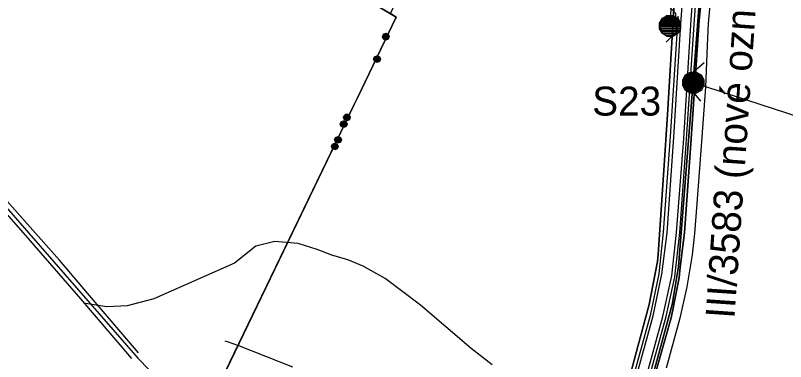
# Model space of a CAD drawing. Extents: x -645676 to -642474, y -1077513 to -1072613.
# Drawn here: x -644954.9 to -644556.1, y -1075498.4 to -1075319 of the extents above; entities that cross this region are included whole.
import ezdxf

# ---------------------------------------------------------------- set-up
doc = ezdxf.new("R2010")
doc.units = 0
for name, color, linetype in [('_cesty_Kunci', 7, 'Continuous'), ('Kanalizace', 7, 'Continuous'), ('KULTURY_STAV', 7, 'Continuous'), ('OBVOD_PU', 7, 'Continuous'), ('P__kop___st_vaj_c_', 7, 'Continuous'), ('PC_MIMO_OBV', 7, 'Continuous'), ('PC_NAVRH', 7, 'Continuous'), ('PC_OBJ_POPIS_NAVRH', 7, 'Continuous'), ('PC_OBJEKTY_NAVRH', 7, 'Continuous'), ('PC_STAN_NAVRH', 7, 'Continuous'), ('Popis_silnice_II__a_III__t__dy', 7, 'Continuous'), ('SDELOVACI', 7, 'Continuous'), ('Silnice_II__t__dy_a_III__t__dy', 7, 'Continuous'), ('SPRAV_HR_STAV', 7, 'Continuous'), ('VODOVOD', 7, 'Continuous'), ('VRSTEVNICE', 7, 'Continuous')]:
    doc.layers.add(name, color=color, linetype=linetype)

# ---------------------------------------------------------------- blocks, each defined once
blk = doc.blocks.new('$406')
blk.add_lwpolyline([(-0.19, 0.72), (0.2, 0.72), (0.54, 0.53), (0.73, 0.19), (0.73, -0.2), (0.54, -0.54), (0.2, -0.73), (-0.19, -0.73), (-0.53, -0.54), (-0.72, -0.2), (-0.72, 0.19), (-0.53, 0.53), (-0.2, 0.72), (-0.28, 0.64), (0.28, 0.64), (0.44, 0.56), (-0.44, 0.56), (-0.52, 0.48), (0.52, 0.48), (0.56, 0.4), (-0.55, 0.4), (-0.6, 0.32), (0.6, 0.32), (0.68, 0.24), (-0.59, 0.24), (-0.65, 0.24), (-0.68, 0.16), (0.59, 0.16), (0.68, 0.16), (0.68, 0.08), (-0.59, 0.08), (-0.68, 0.08), (-0.68, 0), (0.59, 0), (0.68, 0), (0.68, -0.08), (-0.59, -0.08), (-0.68, -0.08), (-0.68, -0.16), (0.59, -0.16), (0.68, -0.16), (0.65, -0.24), (-0.62, -0.24), (-0.65, -0.24), (-0.6, -0.32), (0.6, -0.32), (0.56, -0.4), (-0.55, -0.4), (-0.52, -0.48), (0.52, -0.48), (0.44, -0.56), (-0.44, -0.56), (-0.28, -0.64), (0.28, -0.64), (-0.02, -0.69)])
blk = doc.blocks.new('$935')
blk.add_lwpolyline([(-2, -1), (-1, 0), (1, 0), (2, -1)])
blk = doc.blocks.new('2$0620')
for points in [[(-1.07, 0.32), (-0.88, 0.13), (-0.88, -0.14), (-1.07, -0.33), (-1.34, -0.33), (-1.53, -0.14), (-1.53, 0.13), (-1.34, 0.32), (-1.07, 0.32), (-1.08, 0.28), (-1.32, 0.28), (-1.4, 0.2), (-1, 0.2), (-0.92, 0.12), (-1.48, 0.12), (-1.48, 0.04), (-0.92, 0.04), (-0.92, -0.04), (-1.48, -0.04), (-1.48, -0.12), (-0.92, -0.12), (-1, -0.2), (-1.4, -0.2), (-1.32, -0.28), (-1.08, -0.28)], [(1.43, 0.32), (1.62, 0.13), (1.62, -0.14), (1.43, -0.33), (1.16, -0.33), (0.97, -0.14), (0.97, 0.13), (1.16, 0.32), (1.43, 0.32), (1.4, 0.28), (1.16, 0.28), (1.08, 0.2), (1.48, 0.2), (1.56, 0.12), (1, 0.12), (1, 0.04), (1.56, 0.04), (1.56, -0.04), (1, -0.04), (1, -0.12), (1.56, -0.12), (1.48, -0.2), (1.08, -0.2), (1.16, -0.28), (1.4, -0.28)]]:
    blk.add_lwpolyline(points)

msp = doc.modelspace()

# ---------------------------------------------------------------- linework, layer by layer
at = {"layer": '_cesty_Kunci'}
for points in [[(-644891.19, -1075493.8), (-644917.56, -1075462.89), (-644932.09, -1075445.84), (-644947.3, -1075428.72), (-644979.37, -1075392.6), (-645001.52, -1075368.67), (-645051.49, -1075312.64), (-645077.68, -1075284.72), (-645088.58, -1075274.1), (-645102.77, -1075260.47)], [(-644894.59, -1075496.75), (-644920.98, -1075465.81), (-644950.66, -1075431.71), (-644982.71, -1075395.62), (-645004.85, -1075371.7), (-645054.81, -1075315.68), (-645080.9, -1075287.87), (-645091.72, -1075277.32), (-645105.75, -1075264.09)]]:
    msp.add_lwpolyline(points, dxfattribs=at)
at = {"layer": 'Kanalizace'}
for p, q in [((-644846.48, -1075487.59), (-644845.19, -1075488.05)), ((-644845.19, -1075488.05), (-644839.37, -1075490.12))]:
    msp.add_line(p, q, dxfattribs=at)
at = {"layer": 'KULTURY_STAV'}
for points in [[(-644641.24, -1075565.84), (-644614.92, -1075468.8), (-644611.62, -1075449.05), (-644602.57, -1075335.69), (-644598.94, -1075287.94), (-644594.67, -1075231.99), (-644593.88, -1075221.64), (-644593.31, -1075217.27), (-644591.32, -1075202.08), (-644570.53, -1075092.51), (-644563.77, -1075059.63)], [(-644563.77, -1075059.63), (-644570.53, -1075092.51), (-644591.32, -1075202.08), (-644593.31, -1075217.27), (-644593.88, -1075221.64), (-644594.67, -1075231.99), (-644598.94, -1075287.94), (-644602.57, -1075335.69), (-644611.62, -1075449.05), (-644614.92, -1075468.8), (-644641.24, -1075565.84)], [(-644851.08, -1075513.74), (-644779.52, -1075365.17), (-644777.84, -1075361.69), (-644757.68, -1075319.84), (-644760.71, -1075318.03), (-644746.53, -1075289.08), (-644737.59, -1075267.05), (-644736.8, -1075264.15), (-644692.33, -1075274.04), (-644655.11, -1075281.83), (-644643, -1075284.37), (-644621.33, -1075289.98), (-644615.66, -1075293.05), (-644612.56, -1075292.62), (-644616.89, -1075364.66), (-644616.92, -1075365.04), (-644618.52, -1075388.88), (-644622.17, -1075442.97), (-644622.41, -1075446.47), (-644626.67, -1075468.75), (-644631.36, -1075486.14), (-644660.63, -1075594.71)], [(-644660.63, -1075594.71), (-644631.36, -1075486.14), (-644626.67, -1075468.75), (-644622.41, -1075446.47), (-644622.17, -1075442.97), (-644618.52, -1075388.88), (-644616.92, -1075365.04), (-644616.89, -1075364.66), (-644612.56, -1075292.62)], [(-644599.35, -1075305.97), (-644600.88, -1075321.39), (-644605.07, -1075382.91), (-644608.52, -1075431.72), (-644610.65, -1075449.53), (-644611.3, -1075455.01), (-644614.01, -1075468.82), (-644614.04, -1075468.97), (-644615.38, -1075475.8), (-644632.93, -1075537.98)], [(-644632.93, -1075537.98), (-644615.38, -1075475.8), (-644614.04, -1075468.97), (-644614.01, -1075468.82), (-644611.3, -1075455.01), (-644610.65, -1075449.53), (-644608.52, -1075431.72), (-644605.07, -1075382.91), (-644600.88, -1075321.39), (-644599.35, -1075305.97)]]:
    msp.add_lwpolyline(points, dxfattribs=at)
at = {"layer": 'OBVOD_PU'}
msp.add_lwpolyline([(-644851.08, -1075513.74), (-644779.52, -1075365.17), (-644777.84, -1075361.69), (-644757.68, -1075319.84), (-644795.04, -1075297.48), (-644820.35, -1075282.33), (-644850.33, -1075263.32), (-644852.84, -1075262.37), (-644862.38, -1075258.74), (-644863.9, -1075253.24), (-644872.26, -1075252.25), (-644876.28, -1075250.21), (-644887.03, -1075244.75), (-644897.16, -1075239.61), (-644908.34, -1075233.93), (-644928.8, -1075223.41), (-644931.18, -1075222.19), (-644945.57, -1075214.79), (-644951.22, -1075211.54), (-644979.55, -1075195.21)], dxfattribs=at)
at = {"layer": 'P__kop___st_vaj_c_'}
for points in [[(-644655.14, -1075609.48), (-644653.46, -1075602.68), (-644648.86, -1075585.89), (-644635.16, -1075537.38), (-644617.89, -1075475.06), (-644613.54, -1075454.44), (-644610.92, -1075431.54), (-644607.37, -1075383.08), (-644603.3, -1075321.13), (-644601.93, -1075302.47), (-644601.06, -1075291.71), (-644597.72, -1075247.83), (-644595.19, -1075217.3), (-644590.26, -1075186), (-644583.34, -1075151.35), (-644580.44, -1075136.31), (-644575.79, -1075111.27), (-644571.92, -1075092.46)], [(-644611.93, -1075319.33), (-644612.35, -1075328.45), (-644615.83, -1075381.83), (-644619.58, -1075431.28), (-644621.78, -1075452.89), (-644626.25, -1075474.56), (-644642.84, -1075534.64), (-644656.72, -1075584.46), (-644659.11, -1075593.34), (-644661.97, -1075602.58)]]:
    msp.add_lwpolyline(points, dxfattribs=at)
at = {"layer": 'PC_MIMO_OBV'}
for points in [[(-645105.18, -1075262.04), (-645061.38, -1075305.82), (-644985.84, -1075388.74), (-644891.59, -1075496.61)], [(-644891.59, -1075496.61), (-644874.04, -1075514.58), (-644860.84, -1075525.2), (-644849.97, -1075529.08), (-644838.34, -1075530.9)]]:
    msp.add_lwpolyline(points, dxfattribs=at)
at = {"layer": 'PC_NAVRH'}
for points in [[(-644615.94, -1075324.38), (-644614.35, -1075298.06), (-644618.37, -1075293.21), (-644622.69, -1075291.24), (-644738.79, -1075265.15), (-644794.9, -1075254.19), (-644881.17, -1075235.85), (-644890.64, -1075231.29), (-644935.93, -1075197.93), (-645029.58, -1075127.01), (-645122.98, -1075056.71), (-645236.69, -1074970.28), (-645321.72, -1074906.75)], [(-644603.95, -1075353.79), (-644272.56, -1075461.49), (-643996.74, -1075550.91)]]:
    msp.add_lwpolyline(points, dxfattribs=at)
at = {"layer": 'SDELOVACI'}
msp.add_lwpolyline([(-644560.38, -1075075.22), (-644564.89, -1075096.59), (-644567.03, -1075108.6), (-644571.32, -1075129.12), (-644575.46, -1075151.85), (-644577.56, -1075163.27), (-644585.27, -1075204.39), (-644588.56, -1075234.74), (-644591.74, -1075269.83), (-644593.41, -1075290.49), (-644593.66, -1075294.47), (-644596.25, -1075323.14), (-644596.67, -1075334.53), (-644597.63, -1075356.25), (-644600.03, -1075389.03), (-644602.22, -1075418.8), (-644603.31, -1075432), (-644604.47, -1075443.16), (-644607.26, -1075459.62), (-644610.89, -1075475.88), (-644617.87, -1075501.8)], dxfattribs=at)
at = {"layer": 'Silnice_II__t__dy_a_III__t__dy'}
for p, q in [((-644610.11, -1075320.89), (-644608.84, -1075302.23)), ((-644605.01, -1075321.1), (-644603.5, -1075302.41)), ((-644610.45, -1075326), (-644610.11, -1075320.89)), ((-644608.82, -1075382.75), (-644605.01, -1075321.1)), ((-644613.99, -1075382.07), (-644610.45, -1075326)), ((-644617.5, -1075431.67), (-644613.99, -1075382.07)), ((-644612.53, -1075431.45), (-644608.82, -1075382.75)), ((-644620.14, -1075453.12), (-644617.5, -1075431.67)), ((-644615.08, -1075454.01), (-644612.53, -1075431.45)), ((-644624.75, -1075474.74), (-644620.14, -1075453.12)), ((-644619.69, -1075475.08), (-644615.08, -1075454.01)), ((-644641.27, -1075535.22), (-644624.75, -1075474.74)), ((-644636.65, -1075536.99), (-644619.69, -1075475.08))]:
    msp.add_line(p, q, dxfattribs=at)
at = {"layer": 'SPRAV_HR_STAV'}
for p, q in [((-644795.04, -1075297.48), (-644757.68, -1075319.84)), ((-644757.68, -1075319.84), (-644777.84, -1075361.69)), ((-644779.52, -1075365.17), (-644851.08, -1075513.74)), ((-644777.84, -1075361.69), (-644779.52, -1075365.17))]:
    msp.add_line(p, q, dxfattribs=at)
at = {"layer": 'VODOVOD'}
msp.add_line((-644839.37, -1075490.12), (-644811.45, -1075501.1), dxfattribs=at)
at = {"layer": 'VRSTEVNICE'}
msp.add_lwpolyline([(-644708.13, -1075500.09), (-644719, -1075491.6), (-644745.22, -1075469.15), (-644763.46, -1075455.39), (-644774.9, -1075448.87), (-644782.85, -1075445.63), (-644791.12, -1075443.23), (-644798.7, -1075440.29), (-644808.57, -1075437.23), (-644820.51, -1075436.21), (-644830.39, -1075438.66), (-644841.52, -1075447.43), (-644883.23, -1075465.96), (-644897.13, -1075469.58), (-644907.56, -1075470.02), (-644919.73, -1075468.14)], dxfattribs=at)

# ---------------------------------------------------------------- block references
at = {"layer": 'PC_OBJEKTY_NAVRH'}
for p, xscale, yscale, rotation in [((-644613.03, -1075322.82), 4.999999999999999, 5.000000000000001, -89.857368), ((-644604.1, -1075352.99), 5, 4.999999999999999, 85.170132)]:
    msp.add_blockref('$935', p, dxfattribs=dict(at, xscale=xscale, yscale=yscale, rotation=rotation))
at = {"layer": 'PC_STAN_NAVRH', "xscale": 7.5, "yscale": 7.5}
for p in [(-644615.94, -1075324.38), (-644603.95, -1075353.79)]:
    msp.add_blockref('$406', p, dxfattribs=at)
at = {"layer": 'SPRAV_HR_STAV'}
for p, xscale, yscale, rotation in [((-644765.27, -1075335.61), 4.999999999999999, 5, -111.457599), ((-644787.11, -1075380.94), 5, 5.000000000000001, -111.45465300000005), ((-644785.45, -1075377.45), 5.000000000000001, 4.999999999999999, -111.50668999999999)]:
    msp.add_blockref('2$0620', p, dxfattribs=dict(at, xscale=xscale, yscale=yscale, rotation=rotation))

# ---------------------------------------------------------------- texts
at = {"layer": 'PC_OBJ_POPIS_NAVRH'}
msp.add_text('S23', height=15, dxfattribs=at).set_placement((-644656.23, -1075370.89))
at = {"layer": 'Popis_silnice_II__a_III__t__dy'}
msp.add_text('III/3583 (nové označení III/358 25)', height=15, rotation=86.058, dxfattribs=at).set_placement((-644582.62, -1075476.41))

doc.saveas('drawing.dxf')
